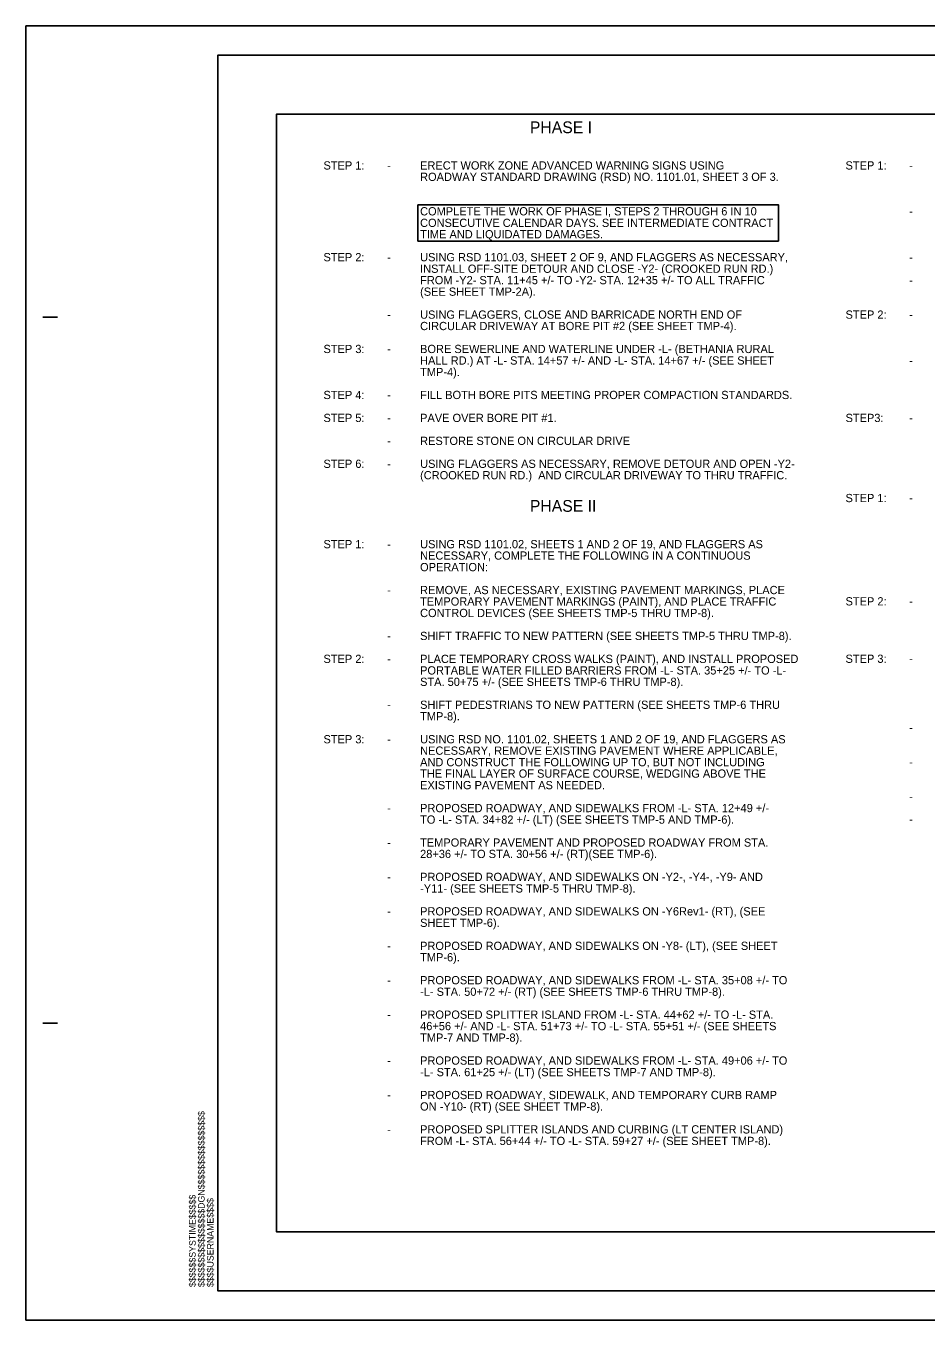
# Model space of a CAD drawing. Extents: x 764226 to 769781, y 650021 to 652521.
# Drawn here: x 766449 to 767214, y 651421 to 652521 of the extents above; entities that cross this region are included whole.
import ezdxf

# ---------------------------------------------------------------- set-up
doc = ezdxf.new("R2010")
doc.units = 0
for name, color, linetype in [('Default', 7, 'Continuous'), ('DEV BORDER CELL', 7, 'Continuous'), ('Scratch_Level_0', 7, 'Continuous'), ('Sheet Plot Border Outside CELL', 7, 'Continuous')]:
    doc.layers.add(name, color=color, linetype=linetype)

msp = doc.modelspace()

# ---------------------------------------------------------------- linework, layer by layer
at = {"layer": 'Default'}
msp.add_lwpolyline([(766782.4, 652369.2), (767088.7, 652369.2), (767088.7, 652338.4), (766782.4, 652338.4)], close=True, dxfattribs=at)
at = {"layer": 'DEV BORDER CELL'}
for p, q in [((766613.3, 652496.3), (766613.3, 652496.3)), ((766463.8, 652273.8), (766476.3, 652273.8)), ((766463.8, 651673.8), (766476.3, 651673.8)), ((766612.3, 651446.3), (766612.3, 651446.3))]:
    msp.add_line(p, q, dxfattribs=at)
msp.add_lwpolyline([(768112.3, 652496.3), (766612.3, 652496.3), (766612.3, 651446.3), (768112.3, 651446.3)], close=True, dxfattribs=at)
at = {"layer": 'Scratch_Level_0'}
msp.add_lwpolyline([(768062.3, 652446.3), (766662.3, 652446.3), (766662.3, 651496.3), (767541.2, 651496.3), (767541.2, 651614.6), (768062.3, 651614.6)], close=True, dxfattribs=at)
at = {"layer": 'Sheet Plot Border Outside CELL'}
msp.add_lwpolyline([(766449.3, 651421.3), (768137.3, 651421.3), (768137.3, 652521.3), (766449.3, 652521.3)], close=True, dxfattribs=at)

# ---------------------------------------------------------------- texts
at = {"layer": 'Default'}
for s, height, p in [('PHASE I', 10, (766877.6, 652430.1)), ('STEP 1:', 7, (766702.2, 652399.2)), ('-', 7, (766756.3, 652399.2)), ('ERECT WORK ZONE ADVANCED WARNING SIGNS USING ', 7, (766784.3, 652399.2)), ('STEP 1:', 7, (767145.8, 652399.2)), ('-', 7, (767199.9, 652399.2)), ('ROADWAY STANDARD DRAWING (RSD) NO. 1101.01, SHEET 3 OF 3.', 7, (766784.3, 652389.5)), ('COMPLETE THE WORK OF PHASE I, STEPS 2 THROUGH 6 IN 10 ', 7, (766784.3, 652360.2)), ('CONSECUTIVE CALENDAR DAYS. SEE INTERMEDIATE CONTRACT ', 7, (766784.3, 652350.4)), ('-', 7, (767199.9, 652360.2)), ('TIME AND LIQUIDATED DAMAGES.', 7, (766784.3, 652340.7)), ('STEP 2:', 7, (766702.2, 652321.2)), ('-', 7, (766756.3, 652321.2)), ('USING RSD 1101.03, SHEET 2 OF 9, AND FLAGGERS AS NECESSARY, ', 7, (766784.3, 652321.2)), ('-', 7, (767199.9, 652321.2)), ('INSTALL OFF-SITE DETOUR AND CLOSE -Y2- (CROOKED RUN RD.) ', 7, (766784.3, 652311.4)), ('FROM -Y2- STA. 11+45 +/- TO -Y2- STA. 12+35 +/- TO ALL TRAFFIC ', 7, (766784.3, 652301.7)), ('-', 7, (767199.9, 652301.7)), ('(SEE SHEET TMP-2A).', 7, (766784.3, 652291.9)), ('USING FLAGGERS, CLOSE AND BARRICADE NORTH END OF ', 7, (766784.3, 652272.4)), ('STEP 2:', 7, (767145.8, 652272.4)), ('-', 7, (766756.3, 652272.4)), ('CIRCULAR DRIVEWAY AT BORE PIT #2 (SEE SHEET TMP-4).', 7, (766784.3, 652262.7)), ('-', 7, (767199.9, 652272.4)), ('STEP 3:', 7, (766702.2, 652243.2)), ('-', 7, (766756.3, 652243.2)), ('BORE SEWERLINE AND WATERLINE UNDER -L- (BETHANIA RURAL ', 7, (766784.3, 652243.2)), ('HALL RD.) AT -L- STA. 14+57 +/- AND -L- STA. 14+67 +/- (SEE SHEET ', 7, (766784.3, 652233.4)), ('-', 7, (767199.9, 652233.4)), ('TMP-4).', 7, (766784.3, 652223.6)), ('STEP 4:', 7, (766702.2, 652204.1)), ('-', 7, (766756.3, 652204.1)), ('FILL BOTH BORE PITS MEETING PROPER COMPACTION STANDARDS.', 7, (766784.3, 652204.1)), ('STEP 5:', 7, (766702.2, 652184.6)), ('PAVE OVER BORE PIT #1.', 7, (766784.3, 652184.6)), ('STEP3:', 7, (767145.8, 652184.6)), ('-', 7, (766756.3, 652184.6)), ('-', 7, (767199.9, 652184.6)), ('-', 7, (766756.3, 652165.1)), ('RESTORE STONE ON CIRCULAR DRIVE', 7, (766784.3, 652165.1)), ('STEP 6:', 7, (766702.2, 652145.6)), ('-', 7, (766756.3, 652145.6)), ('USING FLAGGERS AS NECESSARY, REMOVE DETOUR AND OPEN -Y2- ', 7, (766784.3, 652145.6)), ('(CROOKED RUN RD.)  AND CIRCULAR DRIVEWAY TO THRU TRAFFIC.', 7, (766784.3, 652135.9)), ('PHASE II', 10, (766877.6, 652108.3)), ('STEP 1:', 7, (767145.8, 652116.5)), ('-', 7, (767199.9, 652116.5)), ('STEP 1:', 7, (766702.2, 652077.3)), ('-', 7, (766756.3, 652077.3)), ('USING RSD 1101.02, SHEETS 1 AND 2 OF 19, AND FLAGGERS AS ', 7, (766784.3, 652077.3)), ('NECESSARY, COMPLETE THE FOLLOWING IN A CONTINUOUS ', 7, (766784.3, 652067.6)), ('OPERATION:', 7, (766784.3, 652057.8)), ('-', 7, (766756.3, 652038.3)), ('REMOVE, AS NECESSARY, EXISTING PAVEMENT MARKINGS, PLACE ', 7, (766784.3, 652038.3)), ('TEMPORARY PAVEMENT MARKINGS (PAINT), AND PLACE TRAFFIC ', 7, (766784.3, 652028.6)), ('CONTROL DEVICES (SEE SHEETS TMP-5 THRU TMP-8).', 7, (766784.3, 652018.8)), ('STEP 2:', 7, (767145.8, 652028.7)), ('-', 7, (767199.9, 652028.7)), ('SHIFT TRAFFIC TO NEW PATTERN (SEE SHEETS TMP-5 THRU TMP-8).', 7, (766784.3, 651999.3)), ('-', 7, (766756.3, 651999.3)), ('STEP 2:', 7, (766702.2, 651979.8)), ('-', 7, (766756.3, 651979.8)), ('PLACE TEMPORARY CROSS WALKS (PAINT), AND INSTALL PROPOSED ', 7, (766784.3, 651979.8)), ('STEP 3:', 7, (767145.8, 651979.9)), ('-', 7, (767199.9, 651979.9)), ('PORTABLE WATER FILLED BARRIERS FROM -L- STA. 35+25 +/- TO -L- ', 7, (766784.3, 651970)), ('STA. 50+75 +/- (SEE SHEETS TMP-6 THRU TMP-8).', 7, (766784.3, 651960.3)), ('SHIFT PEDESTRIANS TO NEW PATTERN (SEE SHEETS TMP-6 THRU ', 7, (766784.3, 651940.8)), ('-', 7, (766756.3, 651940.8)), ('TMP-8).', 7, (766784.3, 651931)), ('STEP 3:', 7, (766702.2, 651911.5)), ('USING RSD NO. 1101.02, SHEETS 1 AND 2 OF 19, AND FLAGGERS AS ', 7, (766784.3, 651911.5)), ('-', 7, (767199.9, 651921.4)), ('-', 7, (766756.3, 651911.5)), ('NECESSARY, REMOVE EXISTING PAVEMENT WHERE APPLICABLE, ', 7, (766784.3, 651901.8)), ('AND CONSTRUCT THE FOLLOWING UP TO, BUT NOT INCLUDING ', 7, (766784.3, 651892)), ('-', 7, (767199.9, 651892.1)), ('THE FINAL LAYER OF SURFACE COURSE, WEDGING ABOVE THE ', 7, (766784.3, 651882.3)), ('EXISTING PAVEMENT AS NEEDED.', 7, (766784.3, 651872.5)), ('PROPOSED ROADWAY, AND SIDEWALKS FROM -L- STA. 12+49 +/- ', 7, (766784.3, 651853)), ('-', 7, (767199.9, 651862.9)), ('-', 7, (766756.3, 651853)), ('TO -L- STA. 34+82 +/- (LT) (SEE SHEETS TMP-5 AND TMP-6). ', 7, (766784.3, 651843.2)), ('-', 7, (767199.9, 651843.4)), ('TEMPORARY PAVEMENT AND PROPOSED ROADWAY FROM STA. ', 7, (766784.3, 651823.7)), ('-', 7, (766756.3, 651823.7)), ('28+36 +/- TO STA. 30+56 +/- (RT)(SEE TMP-6).', 7, (766784.3, 651814)), ('-', 7, (766756.3, 651794.5)), ('PROPOSED ROADWAY, AND SIDEWALKS ON -Y2-, -Y4-, -Y9- AND ', 7, (766784.3, 651794.5)), ('-Y11- (SEE SHEETS TMP-5 THRU TMP-8).', 7, (766784.3, 651784.7)), ('PROPOSED ROADWAY, AND SIDEWALKS ON -Y6Rev1- (RT), (SEE ', 7, (766784.3, 651765.2)), ('-', 7, (766756.3, 651765.2)), ('SHEET TMP-6).', 7, (766784.3, 651755.5)), ('-', 7, (766756.3, 651735.9)), ('PROPOSED ROADWAY, AND SIDEWALKS ON -Y8- (LT), (SEE SHEET ', 7, (766784.3, 651735.9)), ('TMP-6).', 7, (766784.3, 651726.2)), ('-', 7, (766756.3, 651706.7)), ('PROPOSED ROADWAY, AND SIDEWALKS FROM -L- STA. 35+08 +/- TO ', 7, (766784.3, 651706.7)), ('-L- STA. 50+72 +/- (RT) (SEE SHEETS TMP-6 THRU TMP-8).', 7, (766784.3, 651696.9)), ('PROPOSED SPLITTER ISLAND FROM -L- STA. 44+62 +/- TO -L- STA. ', 7, (766784.3, 651677.4)), ('-', 7, (766756.3, 651677.4)), ('46+56 +/- AND -L- STA. 51+73 +/- TO -L- STA. 55+51 +/- (SEE SHEETS ', 7, (766784.3, 651667.7)), ('TMP-7 AND TMP-8).', 7, (766784.3, 651657.9)), ('-', 7, (766756.3, 651638.4)), ('PROPOSED ROADWAY, AND SIDEWALKS FROM -L- STA. 49+06 +/- TO ', 7, (766784.3, 651638.4)), ('-L- STA. 61+25 +/- (LT) (SEE SHEETS TMP-7 AND TMP-8).', 7, (766784.3, 651628.6)), ('-', 7, (766756.3, 651609.1)), ('PROPOSED ROADWAY, SIDEWALK, AND TEMPORARY CURB RAMP ', 7, (766784.3, 651609.1)), ('ON -Y10- (RT) (SEE SHEET TMP-8).', 7, (766784.3, 651599.4)), ('PROPOSED SPLITTER ISLANDS AND CURBING (LT CENTER ISLAND) ', 7, (766784.3, 651579.9)), ('-', 7, (766756.3, 651579.9)), ('FROM -L- STA. 56+44 +/- TO -L- STA. 59+27 +/- (SEE SHEET TMP-8).', 7, (766784.3, 651570.1))]:
    msp.add_text(s, height=height, rotation=359.9999, dxfattribs=at).set_placement(p)
at = {"layer": 'DEV BORDER CELL'}
for s, p in [('$$$$$$$$$$$$$$$$DGN$$$$$$$$$$$$$$$$', (766601.2, 651449.4)), ('$$$$$$SYSTIME$$$$$', (766593.6, 651449.4)), ('$$$$USERNAME$$$$', (766608.8, 651449.4))]:
    msp.add_text(s, height=5.584, rotation=90, dxfattribs=at).set_placement(p)

doc.saveas('drawing.dxf')
